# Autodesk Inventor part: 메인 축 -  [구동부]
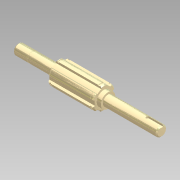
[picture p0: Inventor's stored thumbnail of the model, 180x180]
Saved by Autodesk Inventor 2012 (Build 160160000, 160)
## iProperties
Created: 2012-05
Part Number: 메인 축 -  [구동부]
Document SubType Name: 모델링
Designer: SeoGD™
Mass: 168.566 g
Surface Area: 72.5109 cm^2
Volume: 21.4461 cm^3
Density: 7.86 g/cm^3
Material: 강, 연강
변환 표준: STEP AP214IS
파일 이름: C:\Users\SeoGD\Desktop\?쒗뿕\硫붿씤 異?.stp
전처리기: Build: 253, Release: 2010 SP1 - Date: Wed 07/29/2009
전송 단위: 밀리미터
불확실성: 0.01
Author: SeoGD™
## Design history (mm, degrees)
sketch "스케치1"
  geometry: L1 (-69.5, 0)-(69.5, 0); L2 (69.5, 0)-(69.5, 5); L3 (69.5, 5)-(55.5, 5); L4 (55.5, 5)-(55.5, 4.8); L5 (55.5, 4.8)-(54.35, 4.8); L6 (54.35, 4.8)-(54.35, 5); L7 (54.35, 5)-(30.5, 5); L8 (30.5, 5)-(30.5, 9); L9 (30.5, 9)-(-13.5, 9); L10 (-13.5, 9)-(-13.5, 7); L11 (-13.5, 7)-(-17.5, 7); L12 (-17.5, 7)-(-17.5, 5); L13 (-17.5, 5)-(-69.5, 5); L14 (-69.5, 5)-(-69.5, 0); 2 further points
  constraints: 28 end point, 9 parallel, 4 collinear, 2 perpendicular, 1 coincident, 1 horizontal, 1 midpoint
  dimensions: "d2" = 1.15 distance between parallel lines of L6 L4; "d3" = 10 diameter of L3 L1; "d4" = 9.6 diameter of L5 L1; "d6" = 44 distance between parallel lines of L10 L8; "d7" = 4 distance between parallel lines of L12 L10; "d8" = 14 diameter of L11 L1; "d9" = 18 diameter of L9 L1; "d33" = 52 distance from line of L12.end L14; "d37" = 39 distance between parallel lines of L8 L2; "d38" = 14 distance between parallel lines of L2 L4
revolve "회전1" sketch "스케치1" stored, may be unused: angle "d10" = 90 deg
sketch "스케치2"
  geometry: L1 (2.5, 10.712)-(2.5, 8.646); L2 (-2.5, 10.712)-(-2.5, 8.646); A1 r 9 centre (0, 0) between (2.5, 8.646) and (-2.5, 8.646) reference; A2 r 11 centre (0, 0) between (2.5, 10.712) and (-2.5, 10.712); 1 further point
  constraints: 4 end point, 4 point on circle, 2 parallel, 1 centre point, 1 coincident, 1 vertical
  dimensions: "d11" = 22 diameter of A2; "d12" = 5 distance between parallel lines of L1 L2
extrude "돌출1" join sketch "스케치2" stored distance "d13" = 10; taper "d14" = 0 deg
chamfer "모따기1" distance "d15" = 1; stored, may be unused: second distance "d16" = 2, angle "d17" = 45 deg
node "작업 평면1"
node "작업 평면2"
sketch "스케치3"
  geometry: L1 (2.5, 10.712)-(2.5, 10.198); L2 (-2.5, 10.712)-(-2.5, 10.198); A1 r 11 centre (0, 0) between (2.5, 10.712) and (-2.5, 10.712) reference; A2 r 10.5 centre (0, 0) between (2.5, 10.198) and (-2.5, 10.198); 1 further point
  constraints: 4 end point, 2 point on circle, 1 centre point, 1 coincident, 1 parallel, 1 vertical
  dimensions: "d19" = 21 diameter of A2
extrude "돌출2" cut sketch "스케치3" distance "d20" = 1.35; taper "d21" = 0 deg
node "작업 평면3"
sketch "스케치4"
  geometry: L1 (-26, -5)-(-26, 5) reference; L2 (-26, 1.5)-(-12.5, 1.5); L3 (-12.5, -1.5)-(-26, -1.5); A1 r 1.5 centre (-12.5, 0) between (-12.5, -1.5) and (-12.5, 1.5); 2 further points
  constraints: 4 end point, 2 perpendicular, 2 point on circle, 2 point on line, 2 tangent, 1 centre point, 1 horizontal alignment, 1 midpoint
  dimensions: "d25" = 3 distance between parallel lines of L3 L2; "d26" = 15 dimension on A1 L1
extrude "돌출3" cut sketch "스케치4" distance "d27" = 1.8; taper "d28" = 0 deg
chamfer "모따기2" distance "d29" = 1; stored, may be unused: second distance "d30" = 2, angle "d31" = 45 deg
node "솔리드1"
node "솔리드 본체"
node "곡면 본체"
mirror "대칭1"
pattern_circular "원형 패턴1" dims "d23" = 360 deg
node "솔리드2"
other parameters: "d18" = -1.65
